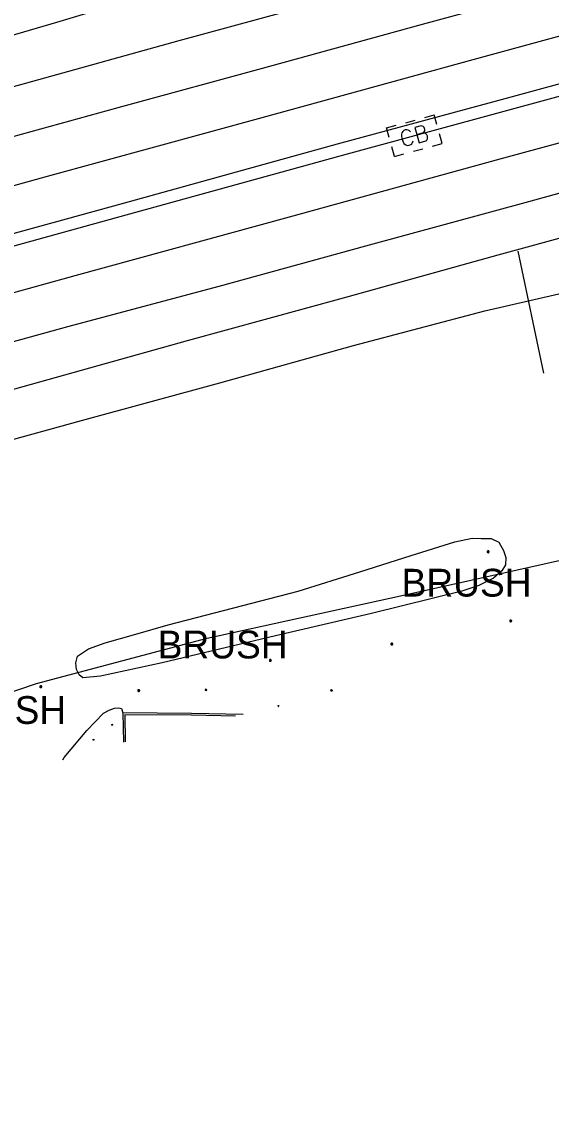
# Model space of a CAD drawing. Extents: x 2129547 to 2134906, y 657330 to 659734.
# Drawn here: x 2130398.1 to 2130531.7, y 657733.1 to 658008.1 of the extents above; entities that cross this region are included whole.
import ezdxf

# ---------------------------------------------------------------- set-up
doc = ezdxf.new("R2010")
doc.units = 0
for name, color, linetype in [('Default', 7, 'Continuous'), ('DR_X_Cells', 7, 'Continuous'), ('LT_X_Poles', 7, 'Continuous'), ('PM_X_Edge_Line', 7, 'Continuous'), ('PM_X_Lane_Line', 7, 'Continuous'), ('PV_X_Curb', 7, 'Continuous'), ('PV_X_EOP2', 7, 'Continuous'), ('PV_X_Parking_Lot', 7, 'Continuous'), ('RD_X_Concrete_Barrier', 7, 'Continuous'), ('RD_X_Fence', 7, 'Continuous'), ('SN_X_Cantilever_Overhead', 7, 'Continuous'), ('VG_X_Cells', 7, 'Continuous'), ('VG_X_Flower_Bed', 7, 'Continuous'), ('VG_X_Shrub_Line_Lt', 7, 'Continuous'), ('VG_X_Text', 7, 'Continuous')]:
    doc.layers.add(name, color=color, linetype=linetype)

# ---------------------------------------------------------------- blocks, each defined once
blk = doc.blocks.new('POINT_DISPLAY')
at = {"layer": 'Default'}
blk.add_line((0, 0), (0, 0), dxfattribs=at)
blk = doc.blocks.new('GCB-X')
at = {"layer": 'Default'}
for p, q in [((-0.0317, 0.019), (-0.019, 0.019)), ((-0.0317, 0.0063), (-0.0317, 0.019)), ((-0.0063, 0.019), (0.0063, 0.019)), ((0.019, 0.019), (0.0317, 0.019)), ((0.0317, 0.0063), (0.0317, 0.019)), ((0.0034, 0.0007), (0.0124, 0.0007)), ((-0.0317, -0.019), (-0.0317, -0.0063)), ((0.0317, -0.019), (0.0317, -0.0063)), ((-0.0317, -0.019), (-0.019, -0.019)), ((-0.0063, -0.019), (0.0063, -0.019)), ((0.019, -0.019), (0.0317, -0.019))]:
    blk.add_line(p, q, dxfattribs=at)
blk.add_lwpolyline([(0.0116, 0.0099), (0.0034, 0.0099), (0.0034, -0.0104), (0.0124, -0.0104)], dxfattribs=at)
for centre, radius, start, end in [((0.0071, 0), 0.0233, 164.8107, 195.1893), ((-0.0094, 0.0037), 0.00645, 21.5603, 158.4397), ((0.0101, 0.0051), 0.00501, 296.8207, 73.0013), ((0.0101, -0.0049), 0.00597, 292.0547, 67.9453), ((-0.0094, -0.0037), 0.00645, 201.5603, 338.4397)]:
    blk.add_arc(centre, radius, start, end, dxfattribs=at)
for p in [(0, 0.019), (0, 0.019), (-0.0317, 0), (0, 0), (0, 0), (0, 0), (0.0317, 0), (0, -0.019), (0, -0.019)]:
    blk.add_blockref('POINT_DISPLAY', p, dxfattribs=at)

msp = doc.modelspace()

# ---------------------------------------------------------------- linework, layer by layer
at = {"layer": 'LT_X_Poles'}
msp.add_lwpolyline([(2130462.88, 657835.71), (2130462.8, 657835.41), (2130462.92, 657835.41)], dxfattribs=at)
msp.add_circle((2130462.84, 657835.56), 0.065, dxfattribs=at)
at = {"layer": 'PM_X_Edge_Line'}
for points in [[(2129783, 657797.65), (2129820.8, 657807.78), (2129922.27, 657836.17), (2129994.45, 657856.25), (2130028.21, 657865.49), (2130093.84, 657883.42), (2130153.98, 657899.99), (2130199.12, 657912.39), (2130249.09, 657926.31), (2130302.49, 657941.01), (2130341.07, 657951.58), (2130345.17, 657952.7), (2130404.65, 657969.17), (2130458.77, 657984.04), (2130511.95, 657998.61), (2130564.35, 658012.89), (2130611.28, 658025.79), (2130665.46, 658040.53), (2130717.36, 658054.84), (2130762.68, 658067.32), (2130806.63, 658079.2), (2130851.4, 658091.68), (2130882.88, 658100.31), (2130891, 658102.57)], [(2129782.31, 657770.56), (2129838.02, 657785.8), (2129918.94, 657807.73), (2130006.57, 657832.43), (2130060.5, 657847.21), (2130112.38, 657861.87), (2130166.66, 657876.43), (2130223.01, 657891.92), (2130282.32, 657908.07), (2130309.12, 657915.87), (2130347.7, 657926.43), (2130352.07, 657927.63), (2130411.57, 657944.11), (2130465.65, 657958.97), (2130518.8, 657973.53), (2130571.22, 657987.81), (2130618.14, 658000.71), (2130672.33, 658015.45), (2130724.27, 658029.78), (2130769.53, 658042.24), (2130813.51, 658054.13), (2130850.23, 658064.39), (2130880.11, 658072.6), (2130898.43, 658077.6)], [(2129783.9, 657836.03), (2129845.86, 657853.1), (2129914.14, 657872.06), (2129982.95, 657891.18), (2130034.97, 657905.36), (2130096.22, 657921.98), (2130157.01, 657938.72), (2130212.56, 657953.66), (2130267.72, 657968.86), (2130293.3, 657975.86), (2130314.89, 657981.71), (2130331.88, 657986.43), (2130357.23, 657993.47), (2130407.01, 658008.01), (2130461.65, 658024.51), (2130507.73, 658038.43), (2130546.43, 658050.14)], [(2129781.33, 657733.06), (2129822.4, 657744.28), (2129902.75, 657766.7), (2130016.9, 657798.42), (2130084.9, 657816.89), (2130135.24, 657830.94), (2130189.26, 657846.05), (2130240.42, 657859.85), (2130282.16, 657871.36), (2130318.23, 657881.32), (2130332.01, 657885.16), (2130356.78, 657892.02), (2130375.64, 657897.24), (2130413.2, 657907.59), (2130448.12, 657917.07), (2130481.79, 657926.44), (2130514.96, 657935.23), (2130533.56, 657939.51)]]:
    msp.add_lwpolyline(points, dxfattribs=at)
at = {"layer": 'PM_X_Lane_Line'}
for points in [[(2129783.61, 657823.91), (2129810.31, 657831.3), (2129849.13, 657842.04), (2129899.17, 657855.99), (2129939.24, 657867.08), (2129976.77, 657877.74), (2130017.08, 657888.49), (2130055.92, 657899.02), (2130096.18, 657909.94), (2130136.01, 657920.82), (2130175.79, 657931.24), (2130213.92, 657941.68), (2130252.44, 657952.34), (2130296.32, 657964.4), (2130319.63, 657970.79), (2130334.89, 657975.01), (2130359.14, 657981.71), (2130397.93, 657992.31), (2130437.8, 658003.41), (2130477.78, 658014.39), (2130517.26, 658025.11), (2130555.6, 658035.62)], [(2129783.29, 657810.14), (2129804.42, 657815.9), (2129840.99, 657826.02), (2129880.02, 657836.71), (2129920.48, 657848.01), (2129956.91, 657858.04), (2129996.24, 657869.42), (2130036.61, 657880.37), (2130073.22, 657890.36), (2130113.36, 657901.36), (2130150.86, 657911.7), (2130189.83, 657922.56), (2130229.83, 657933.62), (2130267.33, 657943.86), (2130299.45, 657952.54), (2130338.02, 657963.15), (2130345.77, 657965.28), (2130383.32, 657975.73), (2130422.46, 657986.54), (2130460.74, 657996.93), (2130499.23, 658007.56), (2130538.61, 658018.28)], [(2129781.97, 657758.13), (2129790.58, 657760.5), (2129829.56, 657771.14), (2129869.63, 657781.89), (2129945.41, 657803.63), (2129982.9, 657813.16), (2130010.71, 657821.32), (2130048.97, 657831.8), (2130087.83, 657842.51), (2130137.07, 657856.3), (2130176.24, 657866.81), (2130213.39, 657877.02), (2130252.97, 657888.01), (2130290.12, 657898.33), (2130312.18, 657904.29), (2130329.72, 657909.17), (2130350.72, 657914.99), (2130369.2, 657920.1), (2130409.79, 657931.31), (2130447.91, 657941.44), (2130484.91, 657951.63), (2130526.03, 657962.85), (2130563.47, 657973.17)], [(2130557.28, 657959.92), (2130518.18, 657949.28), (2130479.22, 657938.42), (2130439.87, 657927.68), (2130400.48, 657916.61), (2130360.47, 657905.46), (2130353.72, 657903.61), (2130321.86, 657894.87), (2130315.15, 657893.02), (2130282.49, 657883.85), (2130241.71, 657872.68), (2130201.93, 657862), (2130163.85, 657851.39), (2130126, 657840.99), (2130086.64, 657830.21), (2130048.06, 657819.28), (2130006.64, 657808.18), (2129969.33, 657798.07), (2129930.34, 657787.23), (2129890.21, 657775.75), (2129850.72, 657764.54), (2129813.2, 657754.11), (2129781.62, 657745.43)]]:
    msp.add_lwpolyline(points, dxfattribs=at)
at = {"layer": 'PV_X_Curb'}
msp.add_lwpolyline([(2130453.99, 657833.38), (2130440.94, 657833.68), (2130423.6, 657833.81), (2130423.76, 657826.42)], dxfattribs=at)
at = {"layer": 'PV_X_EOP2'}
for points in [[(2129783, 657797.65), (2129820.8, 657807.78), (2129922.27, 657836.17), (2129994.45, 657856.25), (2130028.21, 657865.49), (2130093.84, 657883.42), (2130153.98, 657899.99), (2130199.12, 657912.39), (2130249.09, 657926.31), (2130302.49, 657941.01), (2130341.07, 657951.58), (2130345.17, 657952.7), (2130404.65, 657969.17), (2130458.77, 657984.04), (2130511.95, 657998.61), (2130564.35, 658012.89), (2130611.28, 658025.79), (2130665.46, 658040.53), (2130717.36, 658054.84), (2130762.68, 658067.32), (2130806.63, 658079.2), (2130851.4, 658091.68), (2130882.88, 658100.31), (2130891, 658102.57)], [(2129782.31, 657770.56), (2129838.02, 657785.8), (2129918.94, 657807.73), (2130006.57, 657832.43), (2130060.5, 657847.21), (2130112.38, 657861.87), (2130166.66, 657876.43), (2130223.01, 657891.92), (2130282.32, 657908.07), (2130309.12, 657915.87), (2130347.7, 657926.43), (2130352.07, 657927.63), (2130411.57, 657944.11), (2130465.65, 657958.97), (2130518.8, 657973.53), (2130571.22, 657987.81), (2130618.14, 658000.71), (2130672.33, 658015.45), (2130724.27, 658029.78), (2130769.53, 658042.24), (2130813.51, 658054.13), (2130850.23, 658064.39), (2130880.11, 658072.6), (2130898.43, 658077.6)], [(2129783.9, 657836.03), (2129845.86, 657853.1), (2129914.14, 657872.06), (2129982.95, 657891.18), (2130034.97, 657905.36), (2130096.22, 657921.98), (2130157.01, 657938.72), (2130212.56, 657953.66), (2130267.72, 657968.86), (2130293.3, 657975.86), (2130314.89, 657981.71), (2130331.88, 657986.43), (2130357.23, 657993.47), (2130407.01, 658008.01), (2130461.65, 658024.51), (2130507.73, 658038.43), (2130546.43, 658050.14)], [(2129781.33, 657733.06), (2129822.4, 657744.28), (2129902.75, 657766.7), (2130016.9, 657798.42), (2130084.9, 657816.89), (2130135.24, 657830.94), (2130189.26, 657846.05), (2130240.42, 657859.85), (2130282.16, 657871.36), (2130318.23, 657881.32), (2130332.01, 657885.16), (2130356.78, 657892.02), (2130375.64, 657897.24), (2130413.2, 657907.59), (2130448.12, 657917.07), (2130481.79, 657926.44), (2130514.96, 657935.23), (2130533.56, 657939.51)]]:
    msp.add_lwpolyline(points, dxfattribs=at)
at = {"layer": 'PV_X_Parking_Lot'}
msp.add_lwpolyline([(2130452.02, 657832.93), (2130440.93, 657833.18), (2130424.11, 657833.31), (2130424.25, 657826.53)], dxfattribs=at)
at = {"layer": 'RD_X_Concrete_Barrier'}
for points in [[(2130565.99, 658001.27), (2130519.98, 657988.71), (2130477.65, 657977.23), (2130423.68, 657962.34), (2130372.81, 657948.31), (2130344.01, 657940.43), (2130324.59, 657935.12), (2130305.44, 657929.81), (2130253.45, 657915.37), (2130203.07, 657901.49), (2130144.32, 657885.41), (2130086.58, 657869.4), (2130031.8, 657854.67), (2129999.77, 657845.79), (2129936.01, 657828.01), (2129863.42, 657807.87), (2129795.91, 657789.82), (2129782.73, 657786.14)], [(2129782.65, 657783), (2129796.7, 657786.92), (2129864.21, 657804.98), (2129936.81, 657825.12), (2130000.57, 657842.9), (2130032.59, 657851.78), (2130087.37, 657866.51), (2130145.12, 657882.52), (2130203.86, 657898.59), (2130254.25, 657912.48), (2130306.25, 657926.92), (2130325.39, 657932.23), (2130344.78, 657937.53), (2130373.6, 657945.42), (2130424.48, 657959.44), (2130478.44, 657974.34), (2130520.77, 657985.82), (2130566.78, 657998.38)]]:
    msp.add_lwpolyline(points, dxfattribs=at)
at = {"layer": 'RD_X_Fence'}
msp.add_lwpolyline([(2130372.76, 657831.4), (2130401.89, 657841.24), (2130444.91, 657852.66), (2130493.65, 657863.34), (2130547.6, 657875.39), (2130589.68, 657885.4), (2130636.62, 657895.64), (2130749.57, 657921.43), (2130795.47, 657932.48), (2130846.52, 657944.86), (2130897.31, 657956.97), (2130898.55, 657989.46), (2130902.91, 657992.37), (2130925.34, 657969.73), (2130931.96, 657970.88)], dxfattribs=at)
at = {"layer": 'SN_X_Cantilever_Overhead'}
msp.add_line((2130529.78, 657919.52), (2130523.37, 657950.25), dxfattribs=at)
at = {"layer": 'VG_X_Cells'}
for p, q in [((2130444.35, 657839.65), (2130444.6, 657839.65)), ((2130444.6, 657839.65), (2130444.38, 657839.71)), ((2130444.6, 657839.65), (2130444.39, 657839.57)), ((2130444.6, 657839.65), (2130444.4, 657839.76)), ((2130444.6, 657839.65), (2130444.4, 657839.53)), ((2130444.6, 657839.65), (2130444.4, 657839.5)), ((2130444.6, 657839.65), (2130444.43, 657839.82)), ((2130444.6, 657839.65), (2130444.45, 657839.47)), ((2130444.6, 657839.65), (2130444.48, 657839.45)), ((2130444.6, 657839.65), (2130444.52, 657839.43)), ((2130444.6, 657839.65), (2130444.54, 657839.88)), ((2130444.6, 657839.65), (2130444.54, 657839.4)), ((2130444.6, 657839.65), (2130444.57, 657839.42)), ((2130444.6, 657839.65), (2130444.66, 657839.88)), ((2130444.6, 657839.65), (2130444.73, 657839.84)), ((2130444.6, 657839.65), (2130444.78, 657839.79)), ((2130444.6, 657839.65), (2130444.84, 657839.73)), ((2130444.6, 657839.38), (2130444.6, 657839.65)), ((2130444.6, 657839.65), (2130444.65, 657839.42)), ((2130444.6, 657839.65), (2130444.7, 657839.41)), ((2130444.6, 657839.65), (2130444.73, 657839.46)), ((2130444.6, 657839.65), (2130444.78, 657839.47)), ((2130444.6, 657839.65), (2130444.79, 657839.52)), ((2130444.6, 657839.65), (2130444.82, 657839.55)), ((2130444.6, 657839.65), (2130444.84, 657839.6)), ((2130444.6, 657839.65), (2130444.83, 657839.65)), ((2130476.24, 657839.49), (2130476.05, 657839.6)), ((2130476.24, 657839.49), (2130476.07, 657839.66)), ((2130476.24, 657839.49), (2130476.18, 657839.72)), ((2130476.24, 657839.49), (2130476.31, 657839.72)), ((2130476.24, 657839.49), (2130476.38, 657839.68)), ((2130476.24, 657839.49), (2130476.43, 657839.63)), ((2130476, 657839.49), (2130476.24, 657839.49)), ((2130476.24, 657839.49), (2130476.02, 657839.55)), ((2130476.24, 657839.49), (2130476.03, 657839.41)), ((2130476.24, 657839.49), (2130476.04, 657839.37)), ((2130476.24, 657839.49), (2130476.05, 657839.34)), ((2130476.24, 657839.49), (2130476.1, 657839.31)), ((2130476.24, 657839.49), (2130476.13, 657839.29)), ((2130476.24, 657839.49), (2130476.16, 657839.27)), ((2130476.24, 657839.49), (2130476.18, 657839.25)), ((2130476.24, 657839.49), (2130476.22, 657839.26)), ((2130476.24, 657839.49), (2130476.48, 657839.57)), ((2130476.24, 657839.23), (2130476.24, 657839.49)), ((2130476.24, 657839.49), (2130476.29, 657839.26)), ((2130476.24, 657839.49), (2130476.34, 657839.25)), ((2130476.24, 657839.49), (2130476.37, 657839.3)), ((2130476.24, 657839.49), (2130476.42, 657839.31)), ((2130476.24, 657839.49), (2130476.43, 657839.36)), ((2130476.24, 657839.49), (2130476.47, 657839.39)), ((2130476.24, 657839.49), (2130476.48, 657839.44)), ((2130476.24, 657839.49), (2130476.47, 657839.49))]:
    msp.add_line(p, q, dxfattribs=at)
for points in [[(2130420.93, 657830.87), (2130420.96, 657830.91), (2130420.99, 657830.86), (2130421.04, 657830.87), (2130421.02, 657830.81), (2130421.07, 657830.79), (2130421.03, 657830.75), (2130421.04, 657830.7), (2130421, 657830.71), (2130420.99, 657830.66), (2130420.96, 657830.7), (2130420.93, 657830.65), (2130420.91, 657830.7), (2130420.86, 657830.68), (2130420.87, 657830.72), (2130420.83, 657830.72), (2130420.85, 657830.76), (2130420.81, 657830.79), (2130420.85, 657830.8), (2130420.82, 657830.84), (2130420.87, 657830.84), (2130420.86, 657830.89), (2130420.9, 657830.86), (2130420.91, 657830.91), (2130420.93, 657830.87)], [(2130416.25, 657827.12), (2130416.28, 657827.15), (2130416.3, 657827.1), (2130416.35, 657827.11), (2130416.33, 657827.06), (2130416.38, 657827.03), (2130416.34, 657826.99), (2130416.35, 657826.95), (2130416.31, 657826.95), (2130416.3, 657826.91), (2130416.28, 657826.94), (2130416.24, 657826.9), (2130416.22, 657826.94), (2130416.17, 657826.92), (2130416.18, 657826.97), (2130416.14, 657826.97), (2130416.16, 657827), (2130416.12, 657827.03), (2130416.16, 657827.05), (2130416.13, 657827.09), (2130416.18, 657827.08), (2130416.18, 657827.13), (2130416.21, 657827.1), (2130416.22, 657827.15), (2130416.25, 657827.12)]]:
    msp.add_lwpolyline(points, dxfattribs=at)
for centre, radius in [((2130515.8, 657874.45), 0.012), ((2130521.45, 657857), 0.012), ((2130491.49, 657851.17), 0.012), ((2130460.83, 657847.04), 0.012), ((2130402.95, 657840.41), 0.012), ((2130427.64, 657839.41), 0.012), ((2130420.94, 657830.78), 0.0115), ((2130416.25, 657827.03), 0.0115)]:
    msp.add_circle(centre, radius, dxfattribs=at)
for centre, radius, start, end in [((2130515.65, 657874.38), 0.0987, 96.1722, 320.5737), ((2130515.63, 657874.55), 0.0735, 39.0625, 279.5412), ((2130515.75, 657874.62), 0.0658, 354.0047, 205.9741), ((2130515.84, 657874.32), 0.114, 184.9476, 19.4572), ((2130515.89, 657874.59), 0.0776, 323.83, 165.0376), ((2130515.97, 657874.45), 0.0957, 259.1453, 101.4596), ((2130521.29, 657857.09), 0.0735, 39.0625, 279.5412), ((2130521.31, 657856.92), 0.0987, 96.1722, 320.5737), ((2130521.4, 657857.17), 0.0658, 354.0047, 205.9741), ((2130521.5, 657856.87), 0.114, 184.9476, 19.4572), ((2130521.54, 657857.14), 0.0776, 323.83, 165.0376), ((2130521.63, 657857), 0.0957, 259.1453, 101.4596), ((2130491.33, 657851.26), 0.0735, 39.0625, 279.5412), ((2130491.35, 657851.09), 0.0987, 96.1722, 320.5737), ((2130491.44, 657851.34), 0.0658, 354.0047, 205.9741), ((2130491.54, 657851.04), 0.114, 184.9476, 19.4572), ((2130491.58, 657851.31), 0.0776, 323.83, 165.0376), ((2130491.67, 657851.17), 0.0957, 259.1453, 101.4596), ((2130460.66, 657847.13), 0.0735, 39.0625, 279.5412), ((2130460.69, 657846.96), 0.0987, 96.1722, 320.5737), ((2130460.78, 657847.21), 0.0658, 354.0047, 205.9741), ((2130460.88, 657846.91), 0.114, 184.9476, 19.4572), ((2130460.92, 657847.18), 0.0776, 323.83, 165.0376), ((2130461, 657847.04), 0.0957, 259.1453, 101.4596), ((2130402.79, 657840.5), 0.0735, 39.0625, 279.5412), ((2130402.81, 657840.33), 0.0987, 96.1722, 320.5737), ((2130402.9, 657840.57), 0.0658, 354.0047, 205.9741), ((2130403, 657840.28), 0.114, 184.9476, 19.4572), ((2130403.04, 657840.55), 0.0776, 323.83, 165.0376), ((2130403.12, 657840.41), 0.0957, 259.1453, 101.4596), ((2130427.48, 657839.51), 0.0735, 39.0625, 279.5412), ((2130427.59, 657839.58), 0.0658, 354.0047, 205.9741), ((2130427.73, 657839.56), 0.0776, 323.83, 165.0376), ((2130427.5, 657839.34), 0.0987, 96.1722, 320.5737), ((2130427.69, 657839.28), 0.114, 184.9476, 19.4572), ((2130427.82, 657839.42), 0.0957, 259.1453, 101.4596)]:
    msp.add_arc(centre, radius, start, end, dxfattribs=at)
at = {"layer": 'VG_X_Flower_Bed'}
msp.add_lwpolyline([(2130408.46, 657821.94), (2130408.84, 657822.56), (2130414.58, 657829.34), (2130418.75, 657833.7), (2130420.16, 657834.5), (2130421.52, 657834.99), (2130422.59, 657835.11), (2130423.25, 657834.89), (2130423.6, 657833.81)], dxfattribs=at)
at = {"layer": 'VG_X_Shrub_Line_Lt'}
msp.add_lwpolyline([(2130467.81, 657864.52), (2130483.42, 657869.34), (2130496.32, 657873.52), (2130507.37, 657876.95), (2130511.7, 657877.86), (2130514, 657877.82), (2130516.51, 657877.77), (2130518.46, 657876.85), (2130519.64, 657874.77), (2130520.27, 657873.01), (2130520.16, 657871.17), (2130519.19, 657869.63), (2130517.12, 657867.75), (2130513.4, 657865.94), (2130509.1, 657864.5), (2130486.32, 657858.91), (2130462.13, 657853.24), (2130433.55, 657846.41), (2130418.03, 657843.06), (2130413.57, 657842.67), (2130412.57, 657843.4), (2130411.96, 657844.72), (2130411.77, 657846.42), (2130412.21, 657848.12), (2130415, 657849.92), (2130419.13, 657851.5), (2130426.88, 657853.65), (2130435.09, 657856.02)], close=True, dxfattribs=at)

# ---------------------------------------------------------------- block references
at = {"layer": 'DR_X_Cells', "xscale": 196.85, "yscale": 196.84999999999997, "rotation": 15.172744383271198}
msp.add_blockref('GCB-X', (2130497.15, 657979.41), dxfattribs=at)

# ---------------------------------------------------------------- texts
at = {"layer": 'VG_X_Text'}
for p in [(2130493.95, 657863.14), (2130432.42, 657847.53), (2130376.56, 657831.02)]:
    msp.add_text('BRUSH', height=7, dxfattribs=at).set_placement(p)

doc.saveas('drawing.dxf')
